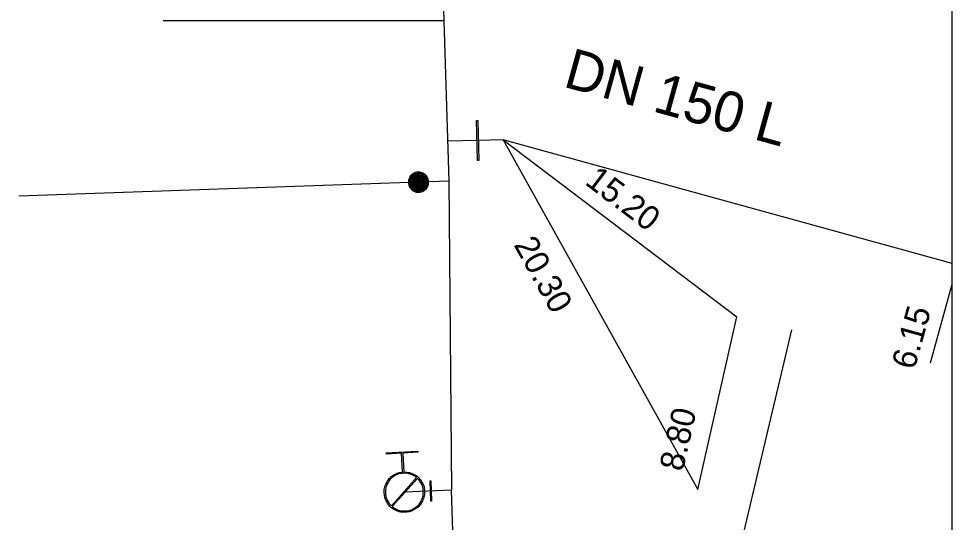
# Model space of a CAD drawing. Extents: x -820257 to -819974, y -1070894 to -1070484.
# Drawn here: x -820022 to -819975.6, y -1070770.22 to -1070745.17 of the extents above; entities that cross this region are included whole.
import ezdxf

# ---------------------------------------------------------------- set-up
doc = ezdxf.new("R2010")
doc.units = 0
for name, color, linetype in [('Default', 7, 'Continuous'), ('Hyd-odbočka', 7, 'Continuous'), ('Hyd-šoupě', 7, 'Continuous'), ('Hydrant', 7, 'Continuous'), ('Oměrka vodovodu', 7, 'Continuous'), ('Oměrka-text', 7, 'Continuous'), ('Přípojka vodovodu', 7, 'Continuous'), ('Přípojkový uzávěr', 7, 'Continuous'), ('Roz-řad', 7, 'Continuous'), ('Roz-řad-popis základní', 7, 'Continuous'), ('Řad-šoupě', 7, 'Continuous')]:
    doc.layers.add(name, color=color, linetype=linetype)

msp = doc.modelspace()

# ---------------------------------------------------------------- linework, layer by layer
at = {"layer": 'Default'}
msp.add_line((-819975.603, -1070893.932), (-819975.603, -1070484.403), dxfattribs=at)
at = {"layer": 'Hyd-odbočka'}
msp.add_line((-820000.485, -1070768.618), (-820002.83, -1070768.712), dxfattribs=at)
at = {"layer": 'Hyd-šoupě'}
msp.add_lwpolyline([(-820001.517, -1070768.159), (-820001.477, -1070769.158), (-820001.508, -1070769.159), (-820001.548, -1070768.16), (-820001.517, -1070768.159)], dxfattribs=at)
at = {"layer": 'Hydrant'}
for points in [[(-820002.921, -1070767.715), (-820002.976, -1070766.779), (-820003.725, -1070766.824), (-820003.728, -1070766.761), (-820002.169, -1070766.669), (-820002.165, -1070766.731), (-820002.914, -1070766.776), (-820002.858, -1070767.712)], [(-820003.477, -1070769.394), (-820002.229, -1070767.989)], [(-820002.184, -1070768.03), (-820003.431, -1070769.436)]]:
    msp.add_lwpolyline(points, dxfattribs=at)
for points in [[(-820002.858, -1070767.712), (-820002.622, -1070767.705), (-820002.39, -1070767.813), (-820002.145, -1070767.928), (-820001.996, -1070768.16), (-820001.847, -1070768.391), (-820001.832, -1070768.653), (-820001.817, -1070768.912), (-820001.934, -1070769.158), (-820002.052, -1070769.403), (-820002.282, -1070769.549), (-820002.512, -1070769.695), (-820002.771, -1070769.71), (-820003.031, -1070769.725), (-820003.276, -1070769.608), (-820003.522, -1070769.49), (-820003.668, -1070769.26), (-820003.813, -1070769.03), (-820003.829, -1070768.771), (-820003.844, -1070768.51), (-820003.724, -1070768.262), (-820003.603, -1070768.014), (-820003.373, -1070767.871), (-820003.158, -1070767.737), (-820002.921, -1070767.715)], [(-820002.229, -1070767.989), (-820002.316, -1070767.918), (-820002.418, -1070767.869), (-820002.65, -1070767.762), (-820002.886, -1070767.776), (-820003.122, -1070767.79), (-820003.339, -1070767.924), (-820003.556, -1070768.058), (-820003.668, -1070768.29), (-820003.781, -1070768.521), (-820003.766, -1070768.767), (-820003.752, -1070769.011), (-820003.614, -1070769.226), (-820003.555, -1070769.32), (-820003.477, -1070769.394)], [(-820003.431, -1070769.436), (-820003.349, -1070769.503), (-820003.248, -1070769.55), (-820003.019, -1070769.662), (-820002.775, -1070769.648), (-820002.531, -1070769.633), (-820002.315, -1070769.496), (-820002.099, -1070769.359), (-820001.99, -1070769.13), (-820001.88, -1070768.9), (-820001.894, -1070768.656), (-820001.909, -1070768.411), (-820002.049, -1070768.194), (-820002.109, -1070768.102), (-820002.184, -1070768.03)]]:
    msp.add_open_spline(points, degree=3, dxfattribs=at)
at = {"layer": 'Oměrka vodovodu'}
for p, q in [((-819997.915, -1070751.199), (-819988.251, -1070768.581)), ((-819997.915, -1070751.199), (-819986.308, -1070759.998)), ((-819976.693, -1070762.292), (-819975.603, -1070758.366)), ((-819988.251, -1070768.581), (-819986.308, -1070759.998)), ((-819988.777, -1070782.56), (-819983.571, -1070760.651))]:
    msp.add_line(p, q, dxfattribs=at)
at = {"layer": 'Přípojka vodovodu'}
msp.add_line((-820000.867, -1070745.267), (-820014.819, -1070745.277), dxfattribs=at)
msp.add_lwpolyline([(-820000.628, -1070753.245), (-820002.127, -1070753.298), (-820021.996, -1070754.003)], dxfattribs=at)
at = {"layer": 'Přípojkový uzávěr'}
for points in [[(-820002.145, -1070752.799), (-820002.019, -1070752.794), (-820001.898, -1070752.855), (-820001.776, -1070752.915), (-820001.704, -1070753.033), (-820001.632, -1070753.151), (-820001.627, -1070753.281), (-820001.623, -1070753.411), (-820001.684, -1070753.532), (-820001.746, -1070753.653), (-820001.863, -1070753.724), (-820001.98, -1070753.794), (-820002.11, -1070753.798), (-820002.239, -1070753.803), (-820002.361, -1070753.741), (-820002.482, -1070753.68), (-820002.552, -1070753.563), (-820002.622, -1070753.447), (-820002.627, -1070753.317), (-820002.631, -1070753.186), (-820002.569, -1070753.063), (-820002.506, -1070752.941), (-820002.389, -1070752.872), (-820002.272, -1070752.803), (-820002.145, -1070752.799)], [(-820002.144, -1070752.846), (-820002.258, -1070752.85), (-820002.364, -1070752.912), (-820002.47, -1070752.974), (-820002.527, -1070753.085), (-820002.584, -1070753.197), (-820002.58, -1070753.315), (-820002.576, -1070753.433), (-820002.512, -1070753.538), (-820002.449, -1070753.644), (-820002.339, -1070753.7), (-820002.229, -1070753.756), (-820002.111, -1070753.751), (-820001.993, -1070753.747), (-820001.887, -1070753.684), (-820001.781, -1070753.62), (-820001.726, -1070753.51), (-820001.67, -1070753.401), (-820001.674, -1070753.283), (-820001.678, -1070753.164), (-820001.744, -1070753.058), (-820001.809, -1070752.951), (-820001.919, -1070752.896), (-820002.029, -1070752.842), (-820002.144, -1070752.846)], [(-820002.142, -1070752.88), (-820002.036, -1070752.876), (-820001.935, -1070752.927), (-820001.833, -1070752.977), (-820001.773, -1070753.076), (-820001.712, -1070753.174), (-820001.708, -1070753.284), (-820001.704, -1070753.393), (-820001.756, -1070753.495), (-820001.807, -1070753.596), (-820001.905, -1070753.655), (-820002.003, -1070753.713), (-820002.113, -1070753.717), (-820002.221, -1070753.721), (-820002.323, -1070753.67), (-820002.425, -1070753.618), (-820002.483, -1070753.52), (-820002.542, -1070753.423), (-820002.546, -1070753.314), (-820002.55, -1070753.204), (-820002.497, -1070753.101), (-820002.445, -1070752.999), (-820002.346, -1070752.941), (-820002.248, -1070752.884), (-820002.142, -1070752.88)], [(-820002.141, -1070752.924), (-820002.297, -1070752.929), (-820002.402, -1070753.043), (-820002.507, -1070753.157), (-820002.502, -1070753.312), (-820002.496, -1070753.468), (-820002.383, -1070753.573), (-820002.269, -1070753.679), (-820002.115, -1070753.673), (-820001.959, -1070753.668), (-820001.853, -1070753.554), (-820001.747, -1070753.441), (-820001.752, -1070753.286), (-820001.758, -1070753.13), (-820001.871, -1070753.024), (-820001.984, -1070752.918), (-820002.141, -1070752.924)], [(-820002.14, -1070752.97), (-820002.003, -1070752.965), (-820001.904, -1070753.057), (-820001.805, -1070753.15), (-820001.8, -1070753.286), (-820001.795, -1070753.422), (-820001.888, -1070753.521), (-820001.98, -1070753.621), (-820002.116, -1070753.626), (-820002.253, -1070753.63), (-820002.352, -1070753.538), (-820002.451, -1070753.445), (-820002.456, -1070753.309), (-820002.461, -1070753.173), (-820002.369, -1070753.074), (-820002.276, -1070752.975), (-820002.14, -1070752.97)], [(-820002.138, -1070753.009), (-820002.258, -1070753.014), (-820002.34, -1070753.101), (-820002.421, -1070753.188), (-820002.416, -1070753.308), (-820002.412, -1070753.427), (-820002.325, -1070753.509), (-820002.238, -1070753.59), (-820002.118, -1070753.586), (-820001.998, -1070753.582), (-820001.917, -1070753.494), (-820001.835, -1070753.407), (-820001.84, -1070753.287), (-820001.844, -1070753.168), (-820001.931, -1070753.086), (-820002.018, -1070753.005), (-820002.138, -1070753.009)], [(-820002.136, -1070753.049), (-820002.031, -1070753.045), (-820001.956, -1070753.116), (-820001.881, -1070753.186), (-820001.877, -1070753.29), (-820001.874, -1070753.394), (-820001.944, -1070753.469), (-820002.015, -1070753.545), (-820002.119, -1070753.548), (-820002.222, -1070753.552), (-820002.297, -1070753.482), (-820002.373, -1070753.411), (-820002.377, -1070753.308), (-820002.381, -1070753.204), (-820002.311, -1070753.128), (-820002.241, -1070753.052), (-820002.136, -1070753.049)], [(-820002.135, -1070753.095), (-820002.219, -1070753.098), (-820002.276, -1070753.16), (-820002.334, -1070753.221), (-820002.331, -1070753.305), (-820002.328, -1070753.39), (-820002.266, -1070753.447), (-820002.205, -1070753.504), (-820002.12, -1070753.501), (-820002.036, -1070753.498), (-820001.979, -1070753.437), (-820001.922, -1070753.375), (-820001.925, -1070753.291), (-820001.928, -1070753.206), (-820001.989, -1070753.149), (-820002.05, -1070753.092), (-820002.135, -1070753.095)], [(-820002.134, -1070753.13), (-820002.063, -1070753.127), (-820002.012, -1070753.175), (-820001.962, -1070753.222), (-820001.959, -1070753.292), (-820001.957, -1070753.362), (-820002.004, -1070753.413), (-820002.052, -1070753.464), (-820002.122, -1070753.466), (-820002.192, -1070753.469), (-820002.243, -1070753.422), (-820002.293, -1070753.374), (-820002.296, -1070753.304), (-820002.298, -1070753.234), (-820002.251, -1070753.183), (-820002.204, -1070753.132), (-820002.134, -1070753.13)], [(-820002.132, -1070753.174), (-820002.184, -1070753.176), (-820002.219, -1070753.213), (-820002.254, -1070753.251), (-820002.252, -1070753.303), (-820002.25, -1070753.355), (-820002.212, -1070753.39), (-820002.174, -1070753.425), (-820002.123, -1070753.424), (-820002.071, -1070753.422), (-820002.036, -1070753.384), (-820002, -1070753.346), (-820002.002, -1070753.294), (-820002.004, -1070753.242), (-820002.042, -1070753.207), (-820002.079, -1070753.172), (-820002.132, -1070753.174)], [(-820002.13, -1070753.221), (-820002.097, -1070753.219), (-820002.074, -1070753.241), (-820002.051, -1070753.263), (-820002.049, -1070753.296), (-820002.048, -1070753.328), (-820002.07, -1070753.352), (-820002.092, -1070753.376), (-820002.125, -1070753.377), (-820002.157, -1070753.378), (-820002.181, -1070753.356), (-820002.204, -1070753.334), (-820002.206, -1070753.301), (-820002.207, -1070753.268), (-820002.185, -1070753.245), (-820002.163, -1070753.222), (-820002.13, -1070753.221)], [(-820002.129, -1070753.252), (-820002.149, -1070753.252), (-820002.162, -1070753.266), (-820002.175, -1070753.28), (-820002.174, -1070753.3), (-820002.174, -1070753.32), (-820002.16, -1070753.333), (-820002.145, -1070753.346), (-820002.126, -1070753.345), (-820002.106, -1070753.345), (-820002.093, -1070753.331), (-820002.08, -1070753.316), (-820002.081, -1070753.297), (-820002.081, -1070753.277), (-820002.095, -1070753.264), (-820002.109, -1070753.251), (-820002.129, -1070753.252)]]:
    msp.add_open_spline(points, degree=3, dxfattribs=at)
at = {"layer": 'Roz-řad'}
msp.add_line((-819999.188, -1070751.224), (-820000.688, -1070751.254), dxfattribs=at)
for points in [[(-820001.582, -1070715.112), (-820001.375, -1070728.801), (-820000.867, -1070745.267)], [(-820000.867, -1070745.267), (-820000.628, -1070753.245), (-820000.485, -1070768.618)], [(-819975.603, -1070757.351), (-819997.915, -1070751.199), (-819999.188, -1070751.224)], [(-819998.171, -1070870.117), (-819998.405, -1070853.152), (-819998.628, -1070844.86), (-819999.183, -1070819.957), (-819999.443, -1070808.28), (-820000.085, -1070782.958), (-820000.381, -1070772.161), (-820000.485, -1070768.618)]]:
    msp.add_lwpolyline(points, dxfattribs=at)
at = {"layer": 'Řad-šoupě'}
msp.add_lwpolyline([(-819999.177, -1070750.224), (-819999.137, -1070752.224), (-819999.2, -1070752.225), (-819999.24, -1070750.225), (-819999.177, -1070750.224)], dxfattribs=at)

# ---------------------------------------------------------------- texts
at = {"layer": 'Oměrka-text'}
for s, rotation, p in [('15.20', 322.8351, (-819993.912, -1070753.371)), ('20.30', 299.0731, (-819997.417, -1070756.411)), (' 6.15', 74.4814, (-819977.605, -1070763.1)), (' 8.80', 77.2445, (-819989.099, -1070768.161))]:
    msp.add_text(s, height=1.2, rotation=rotation, dxfattribs=at).set_placement(p)
at = {"layer": 'Roz-řad-popis základní'}
msp.add_text('DN 150 L', height=2, rotation=344.5851, dxfattribs=at).set_placement((-819994.992, -1070748.536))

doc.saveas('drawing.dxf')
